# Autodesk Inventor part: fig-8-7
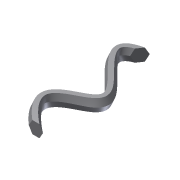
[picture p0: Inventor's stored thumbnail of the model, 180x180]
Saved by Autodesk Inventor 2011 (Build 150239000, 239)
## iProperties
Created: 2006-01
Part Number: fig-8-7
Document SubType Name: Modeling
Designer: CADCIM
Density: 1 g/cm^3
Author: CADCIM
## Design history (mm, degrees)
sketch "Sketch1"
  geometry: 5 further points
  constraints: 5 other
sketch "Sketch2"
  geometry: L1 (-4.728, 0)-(-2.364, 4.094); L2 (-2.364, 4.094)-(2.364, 4.094); L3 (2.364, 4.094)-(4.728, 0); L4 (4.728, 0)-(2.364, -4.094); L5 (2.364, -4.094)-(-2.364, -4.094); L6 (-2.364, -4.094)-(-4.728, 0); 1 further point
  constraints: 12 end point, 13 other
sweep "Sweep4" sketch "Sketch1", "Sketch2" dims "d3" = 0
body "Solid2"
